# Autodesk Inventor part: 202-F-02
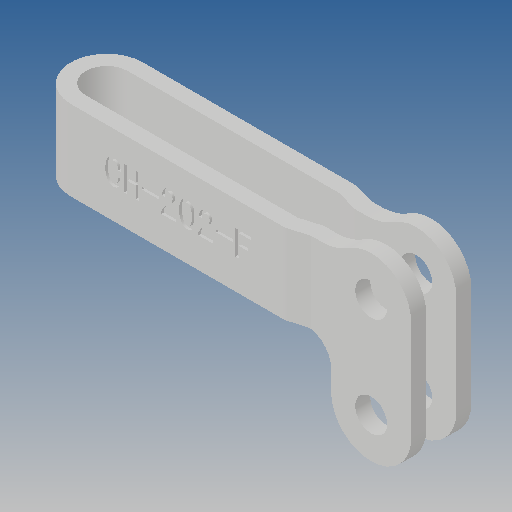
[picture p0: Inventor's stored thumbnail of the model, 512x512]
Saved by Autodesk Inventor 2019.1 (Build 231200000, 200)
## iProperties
Created: 2012-09
Part Number: 202-F-02
Material: Ogólny
Document SubType Name: Modeling
Designer: CADENGINEERING4
Density: 1 g/cm^3
Appearance: Domyślna
Author: CADENGINEERING4
Revision Number: ÈÎºÎ
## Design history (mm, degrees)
feature "ÇÐ³ý-À­Éì4"
node "Bryła1"
